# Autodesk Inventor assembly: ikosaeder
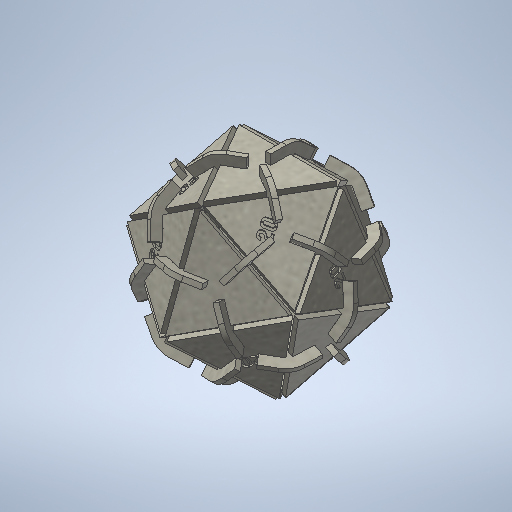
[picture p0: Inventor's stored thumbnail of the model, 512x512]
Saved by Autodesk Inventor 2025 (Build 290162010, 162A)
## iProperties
Created: 2025-02
Part Number: ikosaeder
Material: Generisch
Document SubType Name: Assembly
Designer: BennF
Author: BennF
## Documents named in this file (3)
- C:\Users\BennF\OneDrive - Technische Universität Ilmenau\FabAcademy\week03\ikosaeder.iam
- C:\Users\BennF\OneDrive - Technische Universität Ilmenau\FabAcademy\week03\triangular_tile.ipt
- C:\Users\BennF\OneDrive - Technische Universität Ilmenau\FabAcademy\week03\conector_138.ipt
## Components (50 placed, 2 different names)
1. triangular_tile:1
2. triangular_tile:2 — Mate:10, Mate:11, Mate:12, Mate:19, Mate:20, Mate:21
3. triangular_tile:3 — Mate:13, Mate:14, Mate:15, Mate:34, Mate:35, Mate:36
4. triangular_tile:4 — Mate:16, Mate:17, Mate:18, Mate:49, Mate:50, Mate:51
5. triangular_tile:5 — Mate:22, Mate:23, Mate:24, Mate:25, Mate:26, Mate:27, Mate:64, Mate:65, Mate:66
6. triangular_tile:6 — Mate:28, Mate:29, Mate:30, Mate:31, Mate:32, Mate:33, Mate:67, Mate:68, Mate:69
7. triangular_tile:7 — Mate:37, Mate:38, Mate:39, Mate:40, Mate:41, Mate:42, Mate:70, Mate:71, Mate:72
8. triangular_tile:8 — Mate:43, Mate:44, Mate:45, Mate:46, Mate:47, Mate:48, Mate:73, Mate:74, Mate:75
9. triangular_tile:9 — Mate:52, Mate:53, Mate:54, Mate:55, Mate:56, Mate:57, Mate:76, Mate:77, Mate:78
10. triangular_tile:10 — Mate:58, Mate:59, Mate:60, Mate:61, Mate:62, Mate:63, Mate:79, Mate:80, Mate:81
11. triangular_tile:11 — Mate:82, Mate:83, Mate:84, Mate:109, Mate:110, Mate:111
12. triangular_tile:12 — Mate:85, Mate:86, Mate:87, Mate:100, Mate:101, Mate:102, Mate:112, Mate:113, Mate:114
13. triangular_tile:13 — Mate:88, Mate:89, Mate:90, Mate:115, Mate:116, Mate:117
14. triangular_tile:14 — Mate:91, Mate:92, Mate:93, Mate:103, Mate:104, Mate:105, Mate:118, Mate:119, Mate:120
15. triangular_tile:15 — Mate:94, Mate:95, Mate:96, Mate:121, Mate:122, Mate:123
16. triangular_tile:16
17. triangular_tile:17 — Mate:127, Mate:128, Mate:129, Mate:136, Mate:137, Mate:138
18. triangular_tile:18 — Mate:130, Mate:131, Mate:132, Mate:139, Mate:140, Mate:141
19. triangular_tile:19 — Mate:133, Mate:134, Mate:135, Mate:142, Mate:143, Mate:144
20. triangular_tile:20 — Mate:145, Mate:146, Mate:147
21. conector_138:1 — Mate:1, Mate:2, Mate:3, Mate:10, Mate:11, Mate:12
22. conector_138:2 — Mate:4, Mate:5, Mate:6, Mate:13, Mate:14, Mate:15
23. conector_138:3 — Mate:7, Mate:8, Mate:9, Mate:16, Mate:17, Mate:18
24. conector_138:4 — Mate:19, Mate:20, Mate:21, Mate:22, Mate:23, Mate:24
25. conector_138:5 — Mate:25, Mate:26, Mate:27, Mate:28, Mate:29, Mate:30
26. conector_138:6 — Mate:31, Mate:32, Mate:33
27. conector_138:7 — Mate:34, Mate:35, Mate:36, Mate:37, Mate:38, Mate:39
28. conector_138:8 — Mate:40, Mate:41, Mate:42, Mate:43, Mate:44, Mate:45
29. conector_138:9 — Mate:46, Mate:47, Mate:48
30. conector_138:10 — Mate:49, Mate:50, Mate:51, Mate:52, Mate:53, Mate:54
31. conector_138:11 — Mate:55, Mate:56, Mate:57, Mate:58, Mate:59, Mate:60
32. conector_138:12 — Mate:61, Mate:62, Mate:63
33. conector_138:13 — Mate:64, Mate:65, Mate:66, Mate:82, Mate:83, Mate:84
34. conector_138:14 — Mate:67, Mate:68, Mate:69, Mate:85, Mate:86, Mate:87
35. conector_138:15 — Mate:70, Mate:71, Mate:72, Mate:88, Mate:89, Mate:90
36. conector_138:16 — Mate:73, Mate:74, Mate:75, Mate:91, Mate:92, Mate:93
37. conector_138:17 — Mate:76, Mate:77, Mate:78, Mate:94, Mate:95, Mate:96
38. conector_138:18 — Mate:79, Mate:80, Mate:81, Mate:97, Mate:98, Mate:99
39. conector_138:19 — Mate:100, Mate:101, Mate:102
40. conector_138:20 — Mate:103, Mate:104, Mate:105
41. conector_138:21 — Mate:106, Mate:107, Mate:108
42. conector_138:22 — Mate:109, Mate:110, Mate:111, Mate:127, Mate:128, Mate:129
43. conector_138:23 — Mate:112, Mate:113, Mate:114
44. conector_138:24 — Mate:115, Mate:116, Mate:117, Mate:130, Mate:131, Mate:132
45. conector_138:25 — Mate:118, Mate:119, Mate:120
46. conector_138:26 — Mate:121, Mate:122, Mate:123, Mate:133, Mate:134, Mate:135
47. conector_138:27 — Mate:124, Mate:125, Mate:126
48. conector_138:28 — Mate:136, Mate:137, Mate:138, Mate:145, Mate:146, Mate:147
49. conector_138:29 — Mate:139, Mate:140, Mate:141
50. conector_138:30 — Mate:142, Mate:143, Mate:144
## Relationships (147: Mate 147)
- Mate:1: conector_138:1
- Mate:2: conector_138:1
- Mate:3: conector_138:1
- Mate:4: conector_138:2
- Mate:5: conector_138:2
- Mate:6: conector_138:2
- Mate:7: conector_138:3
- Mate:8: conector_138:3
- Mate:9: conector_138:3
- Mate:10: triangular_tile:2 ↔ conector_138:1
- Mate:11: triangular_tile:2 ↔ conector_138:1
- Mate:12: triangular_tile:2 ↔ conector_138:1
- Mate:13: triangular_tile:3 ↔ conector_138:2
- Mate:14: triangular_tile:3 ↔ conector_138:2
- Mate:15: triangular_tile:3 ↔ conector_138:2
- Mate:16: triangular_tile:4 ↔ conector_138:3
- Mate:17: triangular_tile:4 ↔ conector_138:3
- Mate:18: triangular_tile:4 ↔ conector_138:3
- Mate:19: triangular_tile:2 ↔ conector_138:4
- Mate:20: triangular_tile:2 ↔ conector_138:4
- Mate:21: triangular_tile:2 ↔ conector_138:4
- Mate:22: triangular_tile:5 ↔ conector_138:4
- Mate:23: triangular_tile:5 ↔ conector_138:4
- Mate:24: triangular_tile:5 ↔ conector_138:4
- Mate:25: triangular_tile:5 ↔ conector_138:5
- Mate:26: triangular_tile:5 ↔ conector_138:5
- Mate:27: triangular_tile:5 ↔ conector_138:5
- Mate:28: triangular_tile:6 ↔ conector_138:5
- Mate:29: triangular_tile:6 ↔ conector_138:5
- Mate:30: triangular_tile:6 ↔ conector_138:5
- Mate:31: triangular_tile:6 ↔ conector_138:6
- Mate:32: triangular_tile:6 ↔ conector_138:6
- Mate:33: triangular_tile:6 ↔ conector_138:6
- Mate:34: triangular_tile:3 ↔ conector_138:7
- Mate:35: triangular_tile:3 ↔ conector_138:7
- Mate:36: triangular_tile:3 ↔ conector_138:7
- Mate:37: triangular_tile:7 ↔ conector_138:7
- Mate:38: triangular_tile:7 ↔ conector_138:7
- Mate:39: triangular_tile:7 ↔ conector_138:7
- Mate:40: triangular_tile:7 ↔ conector_138:8
- Mate:41: triangular_tile:7 ↔ conector_138:8
- Mate:42: triangular_tile:7 ↔ conector_138:8
- Mate:43: triangular_tile:8 ↔ conector_138:8
- Mate:44: triangular_tile:8 ↔ conector_138:8
- Mate:45: triangular_tile:8 ↔ conector_138:8
- Mate:46: triangular_tile:8 ↔ conector_138:9
- Mate:47: triangular_tile:8 ↔ conector_138:9
- Mate:48: triangular_tile:8 ↔ conector_138:9
- Mate:49: triangular_tile:4 ↔ conector_138:10
- Mate:50: triangular_tile:4 ↔ conector_138:10
- Mate:51: triangular_tile:4 ↔ conector_138:10
- Mate:52: triangular_tile:9 ↔ conector_138:10
- Mate:53: triangular_tile:9 ↔ conector_138:10
- Mate:54: triangular_tile:9 ↔ conector_138:10
- Mate:55: triangular_tile:9 ↔ conector_138:11
- Mate:56: triangular_tile:9 ↔ conector_138:11
- Mate:57: triangular_tile:9 ↔ conector_138:11
- Mate:58: triangular_tile:10 ↔ conector_138:11
- Mate:59: triangular_tile:10 ↔ conector_138:11
- Mate:60: triangular_tile:10 ↔ conector_138:11
- Mate:61: triangular_tile:10 ↔ conector_138:12
- Mate:62: triangular_tile:10 ↔ conector_138:12
- Mate:63: triangular_tile:10 ↔ conector_138:12
- Mate:64: triangular_tile:5 ↔ conector_138:13
- Mate:65: triangular_tile:5 ↔ conector_138:13
- Mate:66: triangular_tile:5 ↔ conector_138:13
- Mate:67: triangular_tile:6 ↔ conector_138:14
- Mate:68: triangular_tile:6 ↔ conector_138:14
- Mate:69: triangular_tile:6 ↔ conector_138:14
- Mate:70: triangular_tile:7 ↔ conector_138:15
- Mate:71: triangular_tile:7 ↔ conector_138:15
- Mate:72: triangular_tile:7 ↔ conector_138:15
- Mate:73: triangular_tile:8 ↔ conector_138:16
- Mate:74: triangular_tile:8 ↔ conector_138:16
- Mate:75: triangular_tile:8 ↔ conector_138:16
- Mate:76: triangular_tile:9 ↔ conector_138:17
- Mate:77: triangular_tile:9 ↔ conector_138:17
- Mate:78: triangular_tile:9 ↔ conector_138:17
- Mate:79: triangular_tile:10 ↔ conector_138:18
- Mate:80: triangular_tile:10 ↔ conector_138:18
- Mate:81: triangular_tile:10 ↔ conector_138:18
- Mate:82: triangular_tile:11 ↔ conector_138:13
- Mate:83: triangular_tile:11 ↔ conector_138:13
- Mate:84: triangular_tile:11 ↔ conector_138:13
- Mate:85: triangular_tile:12 ↔ conector_138:14
- Mate:86: triangular_tile:12 ↔ conector_138:14
- Mate:87: triangular_tile:12 ↔ conector_138:14
- Mate:88: triangular_tile:13 ↔ conector_138:15
- Mate:89: triangular_tile:13 ↔ conector_138:15
- Mate:90: triangular_tile:13 ↔ conector_138:15
- Mate:91: triangular_tile:14 ↔ conector_138:16
- Mate:92: triangular_tile:14 ↔ conector_138:16
- Mate:93: triangular_tile:14 ↔ conector_138:16
- Mate:94: triangular_tile:15 ↔ conector_138:17
- Mate:95: triangular_tile:15 ↔ conector_138:17
- Mate:96: triangular_tile:15 ↔ conector_138:17
- Mate:97: conector_138:18
- Mate:98: conector_138:18
- Mate:99: conector_138:18
- Mate:100: triangular_tile:12 ↔ conector_138:19
- Mate:101: triangular_tile:12 ↔ conector_138:19
- Mate:102: triangular_tile:12 ↔ conector_138:19
- Mate:103: triangular_tile:14 ↔ conector_138:20
- Mate:104: triangular_tile:14 ↔ conector_138:20
- Mate:105: triangular_tile:14 ↔ conector_138:20
- Mate:106: conector_138:21
- Mate:107: conector_138:21
- Mate:108: conector_138:21
- Mate:109: triangular_tile:11 ↔ conector_138:22
- Mate:110: triangular_tile:11 ↔ conector_138:22
- Mate:111: triangular_tile:11 ↔ conector_138:22
- Mate:112: triangular_tile:12 ↔ conector_138:23
- Mate:113: triangular_tile:12 ↔ conector_138:23
- Mate:114: triangular_tile:12 ↔ conector_138:23
- Mate:115: triangular_tile:13 ↔ conector_138:24
- Mate:116: triangular_tile:13 ↔ conector_138:24
- Mate:117: triangular_tile:13 ↔ conector_138:24
- Mate:118: triangular_tile:14 ↔ conector_138:25
- Mate:119: triangular_tile:14 ↔ conector_138:25
- Mate:120: triangular_tile:14 ↔ conector_138:25
- Mate:121: triangular_tile:15 ↔ conector_138:26
- Mate:122: triangular_tile:15 ↔ conector_138:26
- Mate:123: triangular_tile:15 ↔ conector_138:26
- Mate:124: conector_138:27
- Mate:125: conector_138:27
- Mate:126: conector_138:27
- Mate:127: triangular_tile:17 ↔ conector_138:22
- Mate:128: triangular_tile:17 ↔ conector_138:22
- Mate:129: triangular_tile:17 ↔ conector_138:22
- Mate:130: triangular_tile:18 ↔ conector_138:24
- Mate:131: triangular_tile:18 ↔ conector_138:24
- Mate:132: triangular_tile:18 ↔ conector_138:24
- Mate:133: triangular_tile:19 ↔ conector_138:26
- Mate:134: triangular_tile:19 ↔ conector_138:26
- Mate:135: triangular_tile:19 ↔ conector_138:26
- Mate:136: triangular_tile:17 ↔ conector_138:28
- Mate:137: triangular_tile:17 ↔ conector_138:28
- Mate:138: triangular_tile:17 ↔ conector_138:28
- Mate:139: triangular_tile:18 ↔ conector_138:29
- Mate:140: triangular_tile:18 ↔ conector_138:29
- Mate:141: triangular_tile:18 ↔ conector_138:29
- Mate:142: triangular_tile:19 ↔ conector_138:30
- Mate:143: triangular_tile:19 ↔ conector_138:30
- Mate:144: triangular_tile:19 ↔ conector_138:30
- Mate:145: triangular_tile:20 ↔ conector_138:28
- Mate:146: triangular_tile:20 ↔ conector_138:28
- Mate:147: triangular_tile:20 ↔ conector_138:28
